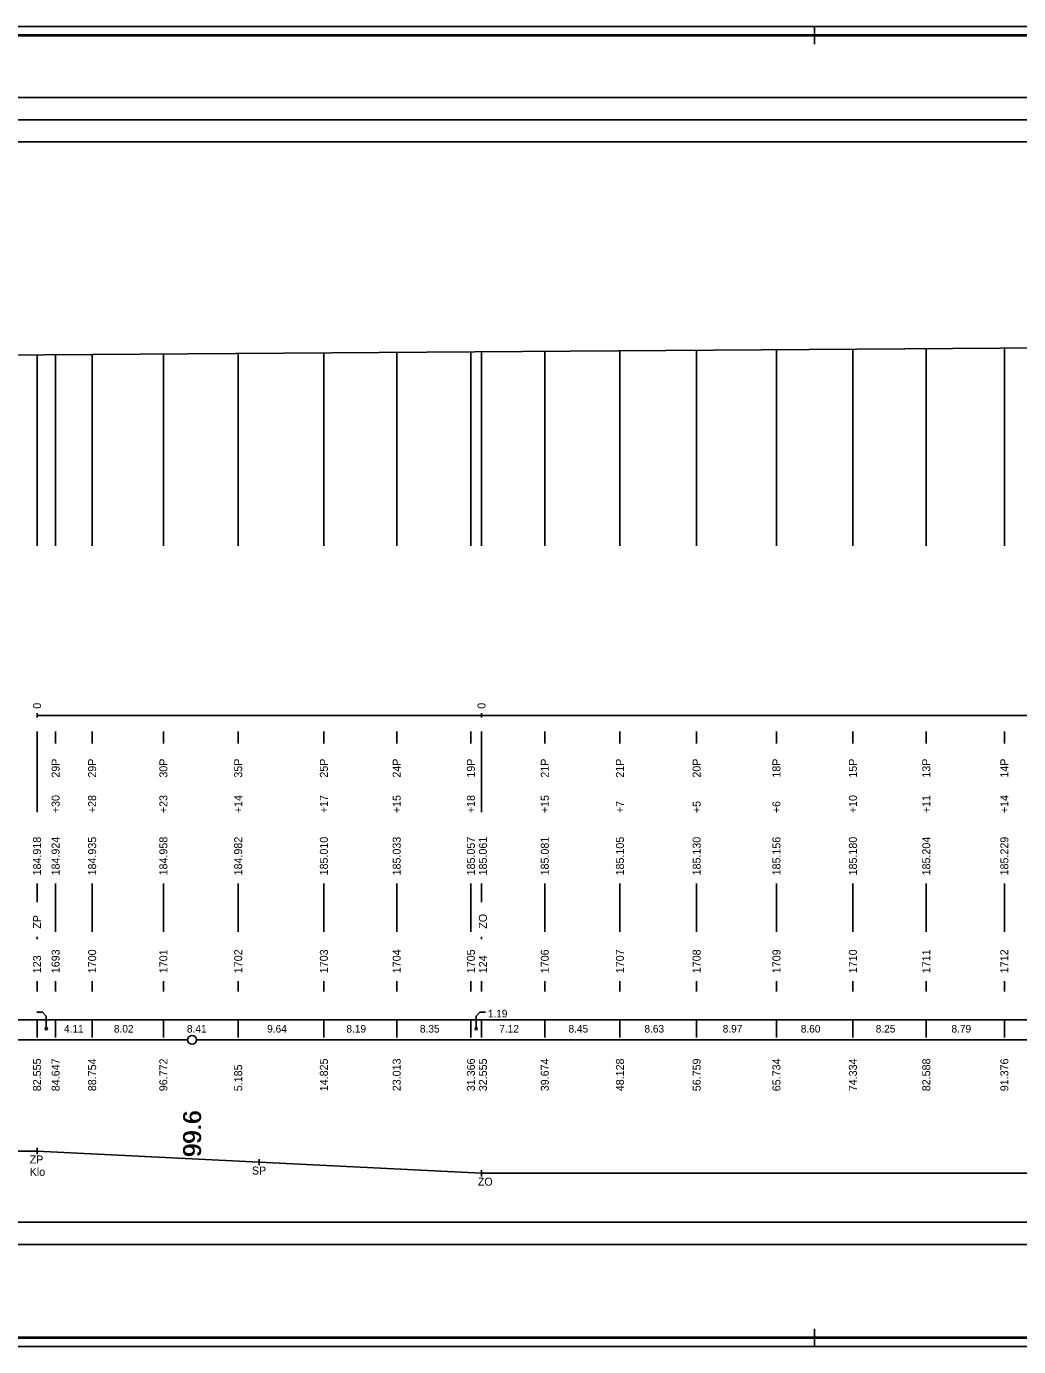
# Model space of a CAD drawing. Extents: x 0 to 10087, y -805 to 297.
# Drawn here: x 6542.7 to 6766, y 0 to 297 of the extents above; entities that cross this region are included whole.
import ezdxf

# ---------------------------------------------------------------- set-up
doc = ezdxf.new("R2010")
doc.units = 0
for name, color, linetype in [('CARKY_HODNOT', 7, 'Continuous'), ('KRIV1_CARA', 7, 'Continuous'), ('KRIV1_TEXT', 7, 'Continuous'), ('NIVELETA_CARA', 7, 'Continuous'), ('PREV_CARA', 7, 'Continuous'), ('PREV_TEXT', 7, 'Continuous'), ('RAM', 7, 'Continuous'), ('REZERVA', 7, 'Continuous'), ('STAN_CARA', 7, 'Continuous'), ('STAN_PAS', 7, 'Continuous'), ('STAN_TEXT', 7, 'Continuous'), ('TEXT', 7, 'Continuous'), ('TXT_C_BODU', 7, 'Continuous')]:
    doc.layers.add(name, color=color, linetype=linetype)

msp = doc.modelspace()

# ---------------------------------------------------------------- linework, layer by layer
at = {"layer": 'CARKY_HODNOT'}
for p, q in [((6545.11, 180.14), (6545.11, 223.09)), ((6549.29, 180.14), (6549.29, 223.12)), ((6557.51, 180.14), (6557.51, 223.18)), ((6573.54, 180.14), (6573.54, 223.29)), ((6590.37, 180.14), (6590.37, 223.41)), ((6609.65, 180.14), (6609.65, 223.55)), ((6626.03, 180.14), (6626.03, 223.67)), ((6642.73, 180.14), (6642.73, 223.79)), ((6645.11, 180.14), (6645.11, 223.8)), ((6659.35, 180.14), (6659.35, 223.91)), ((6676.26, 180.14), (6676.26, 224.03)), ((6693.52, 180.14), (6693.52, 224.15)), ((6711.47, 180.14), (6711.47, 224.28)), ((6728.67, 180.14), (6728.67, 224.4)), ((6745.18, 180.14), (6745.18, 224.52)), ((6762.75, 180.14), (6762.75, 224.65)), ((6545.11, 126.2), (6545.11, 138.35)), ((6549.29, 135.65), (6549.29, 138.35)), ((6557.51, 135.65), (6557.51, 138.35)), ((6573.54, 135.65), (6573.54, 138.35)), ((6590.37, 135.65), (6590.37, 138.35)), ((6609.65, 135.65), (6609.65, 138.35)), ((6626.03, 135.65), (6626.03, 138.35)), ((6642.73, 135.65), (6642.73, 138.35)), ((6645.11, 126.2), (6645.11, 138.35)), ((6659.35, 135.65), (6659.35, 138.35)), ((6676.26, 135.65), (6676.26, 138.35)), ((6693.52, 135.65), (6693.52, 138.35)), ((6711.47, 135.65), (6711.47, 138.35)), ((6728.67, 135.65), (6728.67, 138.35)), ((6745.18, 135.65), (6745.18, 138.35)), ((6762.75, 135.65), (6762.75, 138.35)), ((6545.11, 120.25), (6545.11, 126.2)), ((6645.11, 120.25), (6645.11, 126.2)), ((6545.11, 100), (6545.11, 104.2)), ((6549.29, 93.3), (6549.29, 104.2)), ((6557.51, 93.3), (6557.51, 104.2)), ((6573.54, 93.3), (6573.54, 104.2)), ((6590.37, 93.3), (6590.37, 104.2)), ((6609.65, 93.3), (6609.65, 104.2)), ((6626.03, 93.3), (6626.03, 104.2)), ((6642.73, 93.3), (6642.73, 104.2)), ((6645.11, 100), (6645.11, 104.2)), ((6659.35, 93.3), (6659.35, 104.2)), ((6676.26, 93.3), (6676.26, 104.2)), ((6693.52, 93.3), (6693.52, 104.2)), ((6711.47, 93.3), (6711.47, 104.2)), ((6728.67, 93.3), (6728.67, 104.2)), ((6745.18, 93.3), (6745.18, 104.2)), ((6762.75, 93.3), (6762.75, 104.2)), ((6545.11, 91.65), (6545.11, 92.2)), ((6645.11, 91.65), (6645.11, 92.2)), ((6545.11, 79.9), (6545.11, 82.2)), ((6549.29, 79.9), (6549.29, 82.2)), ((6557.51, 79.9), (6557.51, 82.2)), ((6573.54, 79.9), (6573.54, 82.2)), ((6590.37, 79.9), (6590.37, 82.2)), ((6609.65, 79.9), (6609.65, 82.2)), ((6626.03, 79.9), (6626.03, 82.2)), ((6642.73, 79.9), (6642.73, 82.2)), ((6645.11, 79.9), (6645.11, 82.2)), ((6659.35, 79.9), (6659.35, 82.2)), ((6676.26, 79.9), (6676.26, 82.2)), ((6693.52, 79.9), (6693.52, 82.2)), ((6711.47, 79.9), (6711.47, 82.2)), ((6728.67, 79.9), (6728.67, 82.2)), ((6745.18, 79.9), (6745.18, 82.2)), ((6762.75, 79.9), (6762.75, 82.2))]:
    msp.add_line(p, q, dxfattribs=at)
at = {"layer": 'KRIV1_CARA'}
for p, q in [((6545.11, 44), (6545.11, 44.7)), ((5093.47, 44), (6545.11, 44)), ((6545.11, 44), (6645.11, 39)), ((6545.11, 44), (6545.11, 43.3)), ((6595.11, 41.5), (6595.11, 42.2)), ((6595.11, 41.5), (6595.11, 40.8)), ((6645.11, 39), (6645.11, 39.7)), ((6645.11, 39), (6645.11, 38.3)), ((6645.11, 39), (7238.99, 39))]:
    msp.add_line(p, q, dxfattribs=at)
at = {"layer": 'NIVELETA_CARA'}
for p, q in [((300, 281), (8321.33, 281)), ((300, 276), (8321.33, 276)), ((300, 271), (8321.33, 271)), ((6267.59, 221.1), (6909.24, 225.69)), ((500, 28), (8321.33, 28)), ((500, 23), (8321.33, 23))]:
    msp.add_line(p, q, dxfattribs=at)
at = {"layer": 'PREV_CARA'}
for p, q in [((6545.11, 142), (6645.11, 142)), ((6645.11, 142), (7238.99, 142))]:
    msp.add_line(p, q, dxfattribs=at)
at = {"layer": 'PREV_TEXT'}
for p, q in [((6545.11, 141.5), (6545.11, 142.5)), ((6645.11, 141.5), (6645.11, 142.5)), ((6645.11, 141.5), (6645.11, 142.5))]:
    msp.add_line(p, q, dxfattribs=at)
at = {"layer": 'RAM'}
for p, q in [((8636.33, 297), (0, 297)), ((6720, 293), (6720, 297)), ((8634.33, 295.1), (2, 295.1)), ((8634.33, 295), (2, 295)), ((8634.33, 294.9), (2, 294.9)), ((6720, 0), (6720, 4)), ((0, 0), (8636.33, 0)), ((2, 2.1), (8634.33, 2.1)), ((2, 2), (8634.33, 2)), ((2, 1.9), (8634.33, 1.9))]:
    msp.add_line(p, q, dxfattribs=at)
at = {"layer": 'REZERVA'}
msp.add_circle((6580, 69), 1, dxfattribs=at)
at = {"layer": 'STAN_CARA'}
for p, q in [((6381, 69), (6579, 69)), ((6581, 69), (6779, 69))]:
    msp.add_line(p, q, dxfattribs=at)
at = {"layer": 'STAN_PAS'}
for p, q in [((6546.35, 75.2), (6545.08, 75.2)), ((6547.2, 74.35), (6546.35, 75.2)), ((6547.2, 71.75), (6547.2, 74.35)), ((6643.92, 74.35), (6644.77, 75.2)), ((6643.92, 71.75), (6643.92, 74.35)), ((6644.77, 75.2), (6646.05, 75.2)), ((300, 73.5), (8321.33, 73.5)), ((6545.11, 69.5), (6545.11, 73.5)), ((6549.29, 69.5), (6549.29, 73.5)), ((6557.51, 69.5), (6557.51, 73.5)), ((6573.54, 69.5), (6573.54, 73.5)), ((6590.37, 69.5), (6590.37, 73.5)), ((6609.65, 69.5), (6609.65, 73.5)), ((6626.03, 69.5), (6626.03, 73.5)), ((6642.73, 69.5), (6642.73, 73.5)), ((6645.11, 69.5), (6645.11, 73.5)), ((6659.35, 69.5), (6659.35, 73.5)), ((6676.26, 69.5), (6676.26, 73.5)), ((6693.52, 69.5), (6693.52, 73.5)), ((6711.47, 69.5), (6711.47, 73.5)), ((6728.67, 69.5), (6728.67, 73.5)), ((6745.18, 69.5), (6745.18, 73.5)), ((6762.75, 69.5), (6762.75, 73.5))]:
    msp.add_line(p, q, dxfattribs=at)
for centre in [(6547.2, 71.5), (6643.92, 71.5)]:
    msp.add_circle(centre, 0.25, dxfattribs=at)

# ---------------------------------------------------------------- texts
at = {"layer": 'KRIV1_TEXT'}
for s, p in [('ZP', (6543.46, 41.2)), ('Klo', (6543.46, 38.4)), ('SP', (6593.46, 38.7)), ('ZO', (6644.29, 36.2))]:
    msp.add_text(s, height=1.8, dxfattribs=at).set_placement(p)
at = {"layer": 'PREV_TEXT'}
for p in [(6546.01, 143.5), (6646.01, 143.5)]:
    msp.add_text('0', height=1.8, rotation=90, dxfattribs=at).set_placement(p)
at = {"layer": 'STAN_TEXT'}
for s, p in [('1.19', (6646.52, 74.07)), ('4.11', (6551.18, 70.66)), ('8.02', (6562.41, 70.65)), ('8.41', (6578.84, 70.65)), ('9.64', (6596.89, 70.65)), ('8.19', (6614.72, 70.65)), ('8.35', (6631.26, 70.65)), ('7.12', (6649.11, 70.65)), ('8.45', (6664.69, 70.65)), ('8.63', (6681.77, 70.65)), ('8.97', (6699.38, 70.65)), ('8.60', (6716.95, 70.65)), ('8.25', (6733.81, 70.65)), ('8.79', (6750.85, 70.65))]:
    msp.add_text(s, height=1.7, dxfattribs=at).set_placement(p)
for s, height, p in [('82.555', 1.8, (6546.01, 57.45)), ('84.647', 1.8, (6550.19, 57.45)), ('88.754', 1.8, (6558.41, 57.45)), ('96.772', 1.8, (6574.44, 57.45)), ('5.185', 1.8, (6591.27, 57.45)), ('14.825', 1.8, (6610.55, 57.45)), ('23.013', 1.8, (6626.93, 57.45)), ('31.366', 1.8, (6643.63, 57.45)), ('32.555', 1.8, (6646.33, 57.45)), ('39.674', 1.8, (6660.25, 57.45)), ('48.128', 1.8, (6677.16, 57.45)), ('56.759', 1.8, (6694.42, 57.45)), ('65.734', 1.8, (6712.37, 57.45)), ('74.334', 1.8, (6729.57, 57.45)), ('82.588', 1.8, (6746.08, 57.45)), ('91.376', 1.8, (6763.65, 57.45)), ('    99.6', 4, (6582, 36.84)), ('    99.6', 4, (6582, 36.74)), ('    99.6', 4, (6582, 36.64))]:
    msp.add_text(s, height=height, rotation=90, dxfattribs=at).set_placement(p)
at = {"layer": 'TEXT'}
for s, p in [('29P', (6550.19, 128)), ('29P', (6558.41, 128)), ('30P', (6574.44, 128)), ('35P', (6591.27, 128)), ('25P', (6610.55, 128)), ('24P', (6626.93, 128)), ('19P', (6643.63, 128)), ('21P', (6660.25, 128)), ('21P', (6677.16, 128)), ('20P', (6694.42, 128)), ('18P', (6712.37, 128)), ('15P', (6729.57, 128)), ('13P', (6746.08, 128)), ('14P', (6763.65, 128)), ('+30', (6550.19, 120)), ('+28', (6558.41, 120)), ('+23', (6574.44, 120)), ('+14', (6591.27, 120)), ('+17', (6610.55, 120)), ('+15', (6626.93, 120)), ('+18', (6643.63, 120)), ('+15', (6660.25, 120)), ('+7', (6677.16, 120)), ('+5', (6694.42, 120)), ('+6', (6712.37, 120)), ('+10', (6729.57, 120)), ('+11', (6746.08, 120)), ('+14', (6763.65, 120)), ('184.918', (6546.01, 106)), ('184.924', (6550.19, 106)), ('184.935', (6558.41, 106)), ('184.958', (6574.44, 106)), ('184.982', (6591.27, 106)), ('185.010', (6610.55, 106)), ('185.033', (6626.93, 106)), ('185.057', (6643.63, 106)), ('185.061', (6646.33, 106)), ('185.081', (6660.25, 106)), ('185.105', (6677.16, 106)), ('185.130', (6694.42, 106)), ('185.156', (6712.37, 106)), ('185.180', (6729.57, 106)), ('185.204', (6746.08, 106)), ('185.229', (6763.65, 106)), ('ZP', (6546.01, 94)), ('ZO', (6646.33, 94))]:
    msp.add_text(s, height=1.8, rotation=90, dxfattribs=at).set_placement(p)
at = {"layer": 'TXT_C_BODU'}
for s, p in [('1693', (6550.19, 84)), ('1700', (6558.41, 84)), ('1701', (6574.44, 84)), ('1702', (6591.27, 84)), ('1703', (6610.55, 84)), ('1704', (6626.93, 84)), ('1705', (6643.63, 84)), ('1706', (6660.25, 84)), ('1707', (6677.16, 84)), ('1708', (6694.42, 84)), ('1709', (6712.37, 84)), ('1710', (6729.57, 84)), ('1711', (6746.08, 84)), ('1712', (6763.65, 84)), ('123', (6546.01, 84)), ('124', (6646.33, 84))]:
    msp.add_text(s, height=1.8, rotation=90, dxfattribs=at).set_placement(p)

doc.saveas('drawing.dxf')
